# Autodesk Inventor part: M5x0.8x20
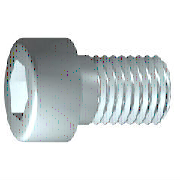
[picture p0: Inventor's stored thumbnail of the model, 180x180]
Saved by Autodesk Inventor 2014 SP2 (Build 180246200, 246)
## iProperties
IsCustomPart: 0
Created: 2015-11
Part Number: M5x0.8x20
Material: 스테인리스강
Description: 6각머리 태핑 나사
Document SubType Name: Modeling
Standard: KS B 1003
Designer: mdu
Standards Organization: KS
Language: ko-KR
Size Designation: M 5 x 20
Categories: <MemberInstance><Categories><Category DisplayName="조임쇠" InternalName="e4da775c-781d-43d5-af7c-5136215cf5a6" Mnemonic="FSTN"><Category DisplayName="볼트" InternalN
Density: 8.08 g/cm^3
Appearance: 반광택
Mass: 5.10181 g
Surface Area: 5.88237 cm^2
Volume: 0.631412 cm^3
Author: mdu
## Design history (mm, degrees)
sketch "스케치1"
  geometry: L1 (-1.167, 0)-(20, 0); L2 (20, 0)-(20, 2.5); L3 (20, 2.5)-(2, 2.5); L4 (2, 2.5)-(1.509, 2.5); L5 (1.509, 2.5)-(0, 2.5); L6 (0, 2.5)-(0, 4.25); L7 (0, 4.25)-(-5, 4.25); L8 (-5, 4.25)-(-5, 2.309); L9 (-5, 2.309)-(-2.5, 2.309); L10 (-2.5, 2.309)-(-1.167, 0); L11 (-10, 0)-(25, 0) reference; L12 (0, -0.85)-(0, 5.1) reference; L13 (2, 2.5)-(0, 2.5)
  constraints: 22 end point, 6 parallel, 2 collinear, 2 perpendicular, 1 horizontal, 1 point on line
  dimensions: "d1" = 18 distance from line of L3.end L2 (= GEL); "d2" = 0.49086 distance of L4.end L3.end (computed from GAL); "d3" = 5 distance between parallel lines of L8 L6 (= KOH); "d4" = 2.5 distance of L8.end L9.end (= INTI); "d5" = 60 deg angle of L10 L1; "d6" = 5 diameter of L3 L1 (= GD); "d7" = 5 diameter of L5 L1 (= BDM); "d8" = 4.6188 diameter of L9 L1 (= 1.1547 x SW); "d9" = 8.5 diameter of L7 L1 (= KOD); "d26" = 20 distance between parallel lines of L12 L2 (= NLG)
revolve "본체" sketch "스케치1" stored, may be unused: angle "d10" = 90 deg
sketch "스케치2"
  geometry: L1 (0, -5.95)-(0, 5.95) reference; L2 (-5.95, 0)-(5.95, 0) reference; L3 (2.309, 0)-(1.155, -2); L4 (1.155, -2)-(-1.155, -2); L5 (-1.155, -2)-(-2.309, 0); L6 (-2.309, 0)-(-1.155, 2); L7 (-1.155, 2)-(1.155, 2); L8 (1.155, 2)-(2.309, 0); 2 further points
  constraints: 12 end point, 1 coincident, 1 horizontal alignment, 1 point on line, 12 other
extrude "슬롯" join sketch "스케치2" stored distance "d11" = 10; taper "d12" = 0 deg
workplane "Work Plane1"
fillet "Fillet2" dims "d30" = 0.1 (= R)
body "Solid1"
fillet "모깎기1" dims "d17" = 0.5 (= RR)
feature "스레드" dims "d13" = 18 (= GEL), "d14" = 0
chamfer "모따기1" distance "d15" = 0.49076 (= -0.5 x SPD + 0.5 x GD); stored, may be unused: second distance "d16" = 0.49076 (= GUL), angle "d27" = 45 deg
other parameters: "GD" = 5 (= NND) [user parameter; used in 2 equation terms], "NLG" = 20 [user parameter; used in 1 equation term], "GEL" = 18 [user parameter; used in 2 equation terms], "KOD" = 8.5 [user parameter; used in 1 equation term], "KOH" = 5 [user parameter; used in 1 equation term], "INTI" = 2.5 [user parameter; used in 1 equation term], "GAL" = 0.49076 (= 0.61345 x PTC) [user parameter; used in 1 equation term], "GUL" = 0.49076 (= 0.61345 x PTC) [user parameter; used in 1 equation term], "BDM" = 5 (= NND) [user parameter; used in 1 equation term], "SW" = 4 [user parameter; used in 2 equation terms], "RR" = 0.5 [user parameter; used in 1 equation term], "SPD" = 4.01848 (= NND - 1.2269 x PTC) [user parameter; used in 1 equation term], "d19" = 0, "d28" = 0, "d29" = 0, "R" = 0.1 [user parameter; used in 1 equation term], "PHH" = 0.2 [user parameter], "GD1" = 4.01848 (= THREADDIA - 1.2269 x PTC) [user parameter], "THREADDIA" = 5 [user parameter; used in 1 equation term], "FAWI" = 45 deg [user parameter], "TPU" = 12.5 (computed from PTC) [user parameter], "PTC" = 0.8 [user parameter; used in 5 equation terms], "NND" = 5 [user parameter; used in 3 equation terms], "TOA" = 30 deg [user parameter], "E0" = 4.62 (= 1.155 x SW) [user parameter]
